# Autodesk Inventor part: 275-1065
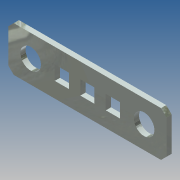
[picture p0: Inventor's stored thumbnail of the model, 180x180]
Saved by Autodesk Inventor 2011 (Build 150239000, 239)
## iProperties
Company: Autodesk Inc.
Created: 2010-06
Part Number: 275-1065
Document SubType Name: Modeling
Designer: Autodesk Inc.
Density: 1 g/cm^3
Catalog Web Link: http://www.vexrobotics.com/275-1065.html
Description: Metal version of the shaft locking part. Three locations for square shafts.
Vendor: Innovation First, Inc.
Author: Autodesk Inc.
Title: VEX Robotics Kit of Parts
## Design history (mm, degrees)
sketch "Sketch1"
  geometry: L1 (0, 10.049)-(-1.238, 8.812); L2 (-1.238, 8.812)-(-1.238, 1.238); L3 (-1.238, 1.238)-(0, 0); L4 (32.974, 0)-(34.212, 1.238); L5 (34.212, 1.238)-(34.212, 8.812); L6 (34.212, 8.812)-(32.974, 10.049); L7 (0, 10.049)-(32.974, 10.049); L8 (0, 0)-(32.974, 0); C1 r 2.311 at (3.787, 5.025); C2 r 2.311 at (29.187, 5.025); 1 further point
  constraints: 16 end point, 2 centre point, 1 parallel, 1 perpendicular
extrude "Extrusion1" new body sketch "Sketch1" distance "d0" = 1.1684; taper "d1" = 0 deg
sketch "Sketch2"
  geometry: L1 (32.974, 10.049)-(0, 10.049) reference; L2 (3.787, 5.025)-(29.187, 5.025); L3 (14.9, 6.612)-(18.075, 6.612); L4 (18.075, 6.612)-(18.075, 3.437); L5 (18.075, 3.437)-(14.9, 3.437); L6 (14.9, 3.437)-(14.9, 6.612); L7 (9.185, 6.612)-(12.36, 6.612); L8 (12.36, 6.612)-(12.36, 3.437); L9 (12.36, 3.437)-(9.185, 3.437); L10 (9.185, 3.437)-(9.185, 6.612); L11 (20.615, 6.612)-(23.79, 6.612); L12 (23.79, 6.612)-(23.79, 3.437); L13 (23.79, 3.437)-(20.615, 3.437); L14 (20.615, 3.437)-(20.615, 6.612); C1 r 2.311 at (29.187, 5.025) reference; C2 r 2.311 at (3.787, 5.025) reference; 9 further points
  constraints: 26 end point, 7 midpoint, 7 parallel, 6 perpendicular, 3 horizontal, 3 horizontal alignment, 3 vertical alignment
  dimensions: "d2" = 3.175 distance of L3.start L3.end; "d3" = 3.175 distance of L7.start L7.end; "d4" = 3.175 distance of L11.start L11.end; "d5" = 2.54 distance between parallel lines of L8 L6; "d6" = 2.54 distance between parallel lines of L14 L4 (= d5)
extrude "Extrusion2" cut sketch "Sketch2" stored distance "d7" = 0.4191; taper "d8" = 0 deg
body "Solid1"
